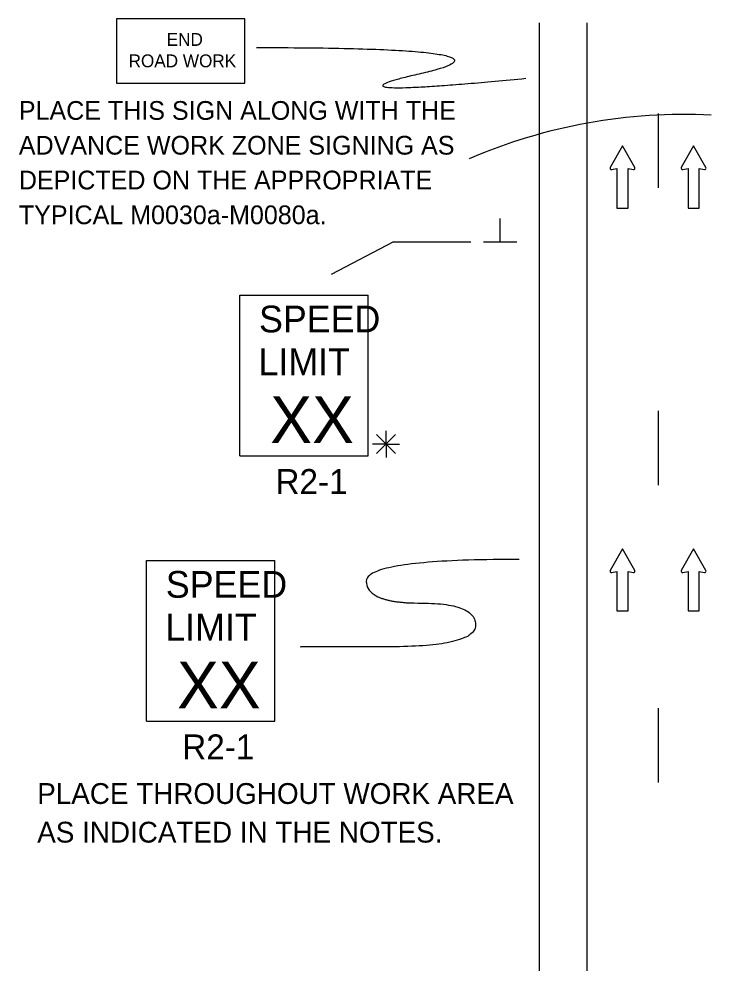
# Model space of a CAD drawing. Extents: x 16737 to 18479, y 5932 to 6964.
# Drawn here: x 16737.7 to 16970.5, y 6610.5 to 6928 of the extents above; entities that cross this region are included whole.
import ezdxf

# ---------------------------------------------------------------- set-up
doc = ezdxf.new("R2010")
doc.units = 0
for name, color, linetype in [('ALI_LEGAL_EX', 7, 'Continuous'), ('MT_SCRATCH_LEVEL_E', 7, 'Continuous'), ('PAVT_EDGE_EX', 7, 'Continuous'), ('TRAFFIC_SIGNS_PR', 7, 'Continuous'), ('TYPICAL_TEXT_DIMEN_PR', 7, 'Continuous')]:
    doc.layers.add(name, color=color, linetype=linetype)

msp = doc.modelspace()

# ---------------------------------------------------------------- linework, layer by layer
at = {"layer": 'ALI_LEGAL_EX'}
for points in [[(16952.72, 6896.22), (16952.72, 6871.22)], [(16952.72, 6796.22), (16952.72, 6771.22)], [(16952.72, 6696.22), (16952.72, 6671.22)]]:
    msp.add_lwpolyline(points, dxfattribs=at)
at = {"layer": 'MT_SCRATCH_LEVEL_E'}
for p, q in [((16940.72, 6885.31), (16936.61, 6878.07)), ((16944.87, 6878.07), (16940.72, 6885.31)), ((16964.62, 6885.31), (16960.51, 6878.07)), ((16968.77, 6878.07), (16964.62, 6885.31)), ((16937.09, 6877.38), (16938.87, 6877.7)), ((16938.87, 6877.7), (16938.87, 6864.44)), ((16942.61, 6864.44), (16942.61, 6877.7)), ((16942.61, 6877.7), (16944.39, 6877.38)), ((16960.99, 6877.38), (16962.77, 6877.7)), ((16962.77, 6877.7), (16962.77, 6864.44)), ((16966.51, 6864.44), (16966.51, 6877.7)), ((16966.51, 6877.7), (16968.29, 6877.38)), ((16938.87, 6864.44), (16942.61, 6864.44)), ((16962.77, 6864.44), (16966.51, 6864.44)), ((16940.72, 6749.79), (16936.61, 6742.55)), ((16944.87, 6742.55), (16940.72, 6749.79)), ((16964.62, 6749.79), (16960.51, 6742.55)), ((16968.77, 6742.55), (16964.62, 6749.79)), ((16937.09, 6741.86), (16938.87, 6742.18)), ((16938.87, 6742.18), (16938.87, 6728.92)), ((16942.61, 6728.92), (16942.61, 6742.18)), ((16942.61, 6742.18), (16944.39, 6741.86)), ((16960.99, 6741.86), (16962.77, 6742.18)), ((16962.77, 6742.18), (16962.77, 6728.92)), ((16966.51, 6728.92), (16966.51, 6742.18)), ((16966.51, 6742.18), (16968.29, 6741.86)), ((16938.87, 6728.92), (16942.61, 6728.92)), ((16962.77, 6728.92), (16966.51, 6728.92))]:
    msp.add_line(p, q, dxfattribs=at)
for centre, start, end in [((16937.02, 6877.84), 150.4248, 279.9638), ((16944.46, 6877.84), 260.0362, 29.7731), ((16960.92, 6877.84), 150.4248, 279.9638), ((16968.36, 6877.84), 260.0362, 29.7731), ((16937.02, 6742.32), 150.4248, 279.9638), ((16944.46, 6742.32), 260.0362, 29.7731), ((16960.92, 6742.32), 150.4248, 279.9638), ((16968.36, 6742.32), 260.0362, 29.7731)]:
    msp.add_arc(centre, 0.463, start, end, dxfattribs=at)
at = {"layer": 'PAVT_EDGE_EX'}
for p, q in [((16912.72, 6926.76), (16912.72, 6164.15)), ((16928.72, 6926.76), (16928.72, 6164.15))]:
    msp.add_line(p, q, dxfattribs=at)
at = {"layer": 'TRAFFIC_SIGNS_PR'}
for p, q in [((16812.01, 6835.14), (16855.21, 6835.14)), ((16812.01, 6781.14), (16812.01, 6835.14)), ((16855.21, 6781.14), (16855.21, 6835.14)), ((16812.01, 6781.14), (16855.21, 6781.14)), ((16780.66, 6745.89), (16823.86, 6745.89)), ((16780.66, 6691.89), (16780.66, 6745.89)), ((16823.86, 6691.89), (16823.86, 6745.89)), ((16780.66, 6691.89), (16823.86, 6691.89))]:
    msp.add_line(p, q, dxfattribs=at)
msp.add_lwpolyline([(16770.56, 6906.45), (16813.76, 6906.45), (16813.76, 6928.05), (16770.56, 6928.05)], close=True, dxfattribs=at)
msp.add_arc((16961.52, 6713.48), 182.45, 87.1671, 113.3806, dxfattribs=at)
msp.add_open_spline([(16817.69, 6918.41), (16911.43, 6918.41), (16834.91, 6900.99), (16908.24, 6908.06)], degree=2, dxfattribs=at)
at = {"layer": 'TYPICAL_TEXT_DIMEN_PR'}
for p, q in [((16899.6, 6853.12), (16899.6, 6860.91)), ((16863.72, 6853.12), (16842.8, 6842.12)), ((16863.72, 6853.12), (16889.72, 6853.12)), ((16893.97, 6853.12), (16905.22, 6853.12)), ((16861.21, 6785.06), (16861.21, 6789.52)), ((16864.4, 6788.25), (16858.02, 6781.88)), ((16858.03, 6788.25), (16864.4, 6781.88)), ((16861.21, 6785.06), (16856.68, 6785.06)), ((16861.21, 6785.06), (16864.4, 6785.06)), ((16861.21, 6785.06), (16865.69, 6785.06)), ((16861.21, 6785.06), (16861.21, 6780.56))]:
    msp.add_line(p, q, dxfattribs=at)
msp.add_open_spline([(16906.02, 6746.26), (16854.57, 6746.26), (16854.57, 6731.56), (16891.32, 6731.56), (16891.32, 6716.86), (16832.52, 6716.86), (16832.52, 6716.86)], degree=2, dxfattribs=at)

# ---------------------------------------------------------------- texts
at = {"layer": 'TRAFFIC_SIGNS_PR'}
for s, height, p in [('END', 4.31, (16787.44, 6918.97)), ('ROAD WORK', 4.31, (16774.63, 6911.78)), ('PLACE THIS SIGN ALONG WITH THE', 6.3, (16737.72, 6894.1)), ('ADVANCE WORK ZONE SIGNING AS', 6.3, (16737.72, 6882.4)), ('DEPICTED ON THE APPROPRIATE', 6.3, (16737.72, 6870.7)), ('TYPICAL M0030a-M0080a.', 6.3, (16737.72, 6859)), ('SPEED', 9, (16818.5, 6822.61)), ('LIMIT', 9, (16818.31, 6808.21)), ('XX', 15.785, (16822.26, 6785.37)), ('R2-1', 8.37, (16824.02, 6768.27)), ('SPEED', 9, (16787.15, 6733.36)), ('LIMIT', 9, (16786.97, 6718.96)), ('XX', 15.785, (16790.91, 6696.12)), ('R2-1', 8.37, (16792.67, 6679.02)), ('PLACE THROUGHOUT WORK AREA', 7, (16743.91, 6664.02)), ('AS INDICATED IN THE NOTES.', 7, (16743.91, 6651.02))]:
    msp.add_text(s, height=height, dxfattribs=at).set_placement(p)

doc.saveas('drawing.dxf')
